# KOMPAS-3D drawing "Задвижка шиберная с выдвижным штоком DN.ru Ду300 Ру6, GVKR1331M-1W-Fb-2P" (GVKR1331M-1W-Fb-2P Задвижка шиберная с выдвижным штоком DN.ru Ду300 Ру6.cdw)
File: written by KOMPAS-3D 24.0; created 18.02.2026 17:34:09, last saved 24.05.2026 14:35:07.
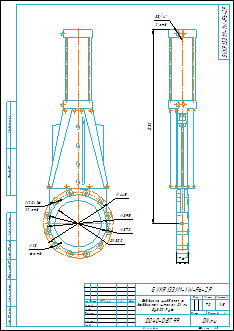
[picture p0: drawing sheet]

Document properties: Автор: R2D2; Форматы листов документа: A3; Полное имя файла: GVKR1331M-1W-Fb-2P Задвижка шиберная с выдвижным штоком DN.ru Ду300 Ру6.m3d; Масса: 70; Наименование: Задвижка шиберная с выдвижным штоком DN.ru Ду300 Ру6; Количество листов документа: 1; Примечание: D040-08799

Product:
- Part/product: Задвижка шиберная с выдвижным штоком DN.ru Ду300 Ру6  | designation GVKR1331M-1W-Fb-2P
    Масса: 70
    Раздел спецификации: Прочие изделия
    Примечание: D040-08799

Views: Вид 1, Спереди, Проекционный вид 2
Referenced files in E:\Работа\Зайцев\GVKR1331N-2W-Fb-S Задвижка шиберная с выдвижным штоком DN.ru Ду50-300 Ру10\DN50\: GVKR1331N-2W-Fb-S Задвижка шиберная DN.ru Ду50 Ру10.m3d
Referenced files in E:\Работа\Зайцев\GVKR1331M-1W-Fb-2P Задвижка шиберная с выдвижным штоком DN.ru Ду50-300 Ру16-10-6 с пневмоприводом\исходные материалы\DN300\DN300\: GVKR1331M-1W-Fb-2P Задвижка шиберная с выдвижным штоком DN.ru Ду300 Ру6.m3d
Referenced files in E:\Работа\Зайцев\Для компаса\: чертеж DN.ru А3.cdt
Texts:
  GVKR1331M-1W-Fb-2P
  чертеж DN.ru А3.cdt
  Задвижка шиберная с
  выдвижным штоком DN.ru
  Ду300 Ру6
  Задвижка шиберная с выдвижным штоком DN.ru Ду300 Ру6
  GVKR1331M-1W-Fb-2P Задвижка шиберная с выдвижным штоком DN.ru Ду300 Ру6
Dimensions and other numbers on the sheet: 0; 3; 2; 4; 20; 12 отв.; 23; 6 отв.; 370; 300; 395; 445; 2 отв.; 76; 1232; 1:5; 1; 70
